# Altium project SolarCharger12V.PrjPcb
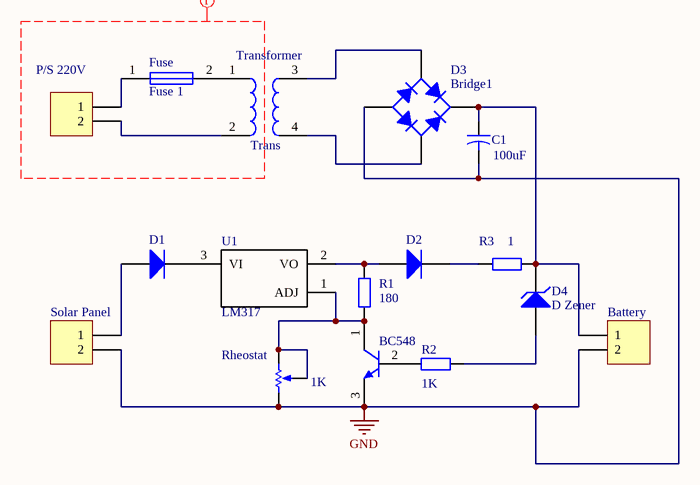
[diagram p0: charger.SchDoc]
1 sheet, 16 parts. Net scope: global (net labels, ports and power ports of the same name join across sheets).
Board file: charger.PcbDoc

## Sheet charger.SchDoc
size A4

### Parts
Battery  Homemade Connector  [Connector (Clamp?)]  (value not drawn)
BC548  BC548BRL1G  [ONSC-TO-92-3-29-11_AM_BL]  (value not drawn)
C1  value 100uF  [CAPR5-4X5]  (hidden comment: Cap2)
D1  Diode 1N4007  [DO-41]  (value not drawn)
D2  Diode 1N4007  [DO-41]  (value not drawn)
D3  Bridge1  [D-38]
D4  D Zener  [Zener Diode]
Fuse  Fuse 1  [Fuse Case]
P/S_220V  Homemade Connector  [Connector (Clamp?)]  (value not drawn)
R1  value 180  [AXIAL-0.4]  (hidden comment: Res2)
R2  value 1K  [AXIAL-0.4]  (hidden comment: Res2)
R3  value 1  [PCBComponent_1]  (hidden comment: ResCustom)
Rheostat  value 1K  [potentiometer (Piher)]  (hidden comment: RPot)
Solar_Panel  Homemade Connector  [Connector (Clamp?)]  (value not drawn)
Transformer  Trans  [Transformer]
U1  LM317  [to220-123-v]

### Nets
GND: Battery.2 BC548.3(E) C1.2 D3.3(A) Rheostat.1(TOP) Solar_Panel.2
NetBattery_1: Battery.1 C1.1 D3.1(K) D4.2(K) R3.2
NetBC548_1: BC548.1(C) R1.1 Rheostat.2(BOT) Rheostat.3(TAP) U1.1(ADJ)
NetBC548_2: BC548.2(B) R2.2
NetD1_1: D1.1(A) Solar_Panel.1
NetD1_2: D1.2(K) U1.3(VI)
NetD2_1: D2.1(A) R1.2 U1.2(VO)
NetD2_2: D2.2(K) R3.1
NetD3_2: D3.2(C) Transformer.4
NetD3_4: D3.4(C) Transformer.3
NetD4_1: D4.1(A) R2.1
NetFuse_1: Fuse.1 P/S_220V.1
NetFuse_2: Fuse.2 Transformer.1
NetP/S_220V_2: P/S_220V.2 Transformer.2

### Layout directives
net class 220V: (no net found under the mark)

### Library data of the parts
Battery P/S_220V Solar_Panel = Header 2: Klema
BC548 = BC548BRL1G: Amplifier Transistor, NPN Silicon, 3-Pin TO-92, Pb-Free, Tape and Reel; Manufacturer: On Semiconductor; fT Min (MHz): 150; IC Continuous (A): 0.1
C1 = Cap2: Capacitor
D1 D2 = Diode 1N4007: 1 Amp General Purpose Rectifier
D3 = Bridge1: Full Wave Diode Bridge
D4 = D Zener: Zener Diode
Fuse = Fuse 1: Fuse
R1 R2 = Res2: Resistor
Rheostat = RPot: Potentiometer; Sim Note: Enter the Resistance value and the set point into parameter fields.; Set Position: 0.5
Transformer = Trans: Transformer TL42S-120-416
U1 = LM317-TO220: LINEAR REGULATOR ADJ POSITIVE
